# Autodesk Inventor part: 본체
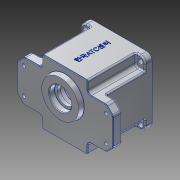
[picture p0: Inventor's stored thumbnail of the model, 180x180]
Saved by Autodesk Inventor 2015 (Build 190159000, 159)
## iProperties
Created: 2016-02
Part Number: 본체
Material: Aluminum 6061
Document SubType Name: Modeling
Designer: Administrator
Density: 2.7 g/cm^3
Appearance: Aluminum - Flat
Mass: 873.756 g
Surface Area: 761.195 cm^2
Volume: 323.613 cm^3
Author: Administrator
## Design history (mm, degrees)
sketch "Sketch1"
  geometry: L1 (-47, -47)-(47, -47); L2 (47, -47)-(47, 47); L3 (47, 47)-(-47, 47); L4 (-47, 47)-(-47, -47); L5 (-47, -47)-(47, 47); L6 (47, -47)-(-47, 47); 1 further point
  constraints: 12 end point, 2 midpoint, 2 parallel, 1 horizontal, 1 perpendicular
  dimensions: "d0" = 94 distance of L3.end L2.end; "d1" = 94 distance of L2.end L1.end
extrude "Extrusion1" new body sketch "Sketch1" distance "d2" = 80; taper "d3" = 0 deg
sketch "Sketch2"
  geometry: L1 (33, -47)-(-33, -47); L2 (-33, -47)-(-33, 47); L3 (-33, 47)-(33, 47); L4 (33, 47)-(33, -47); L5 (33, -47)-(-33, 47); L6 (-33, -47)-(33, 47); L7 (-47, 47)-(47, 47) reference; L8 (47, -30)-(-47, -30); L9 (-47, -30)-(-47, 30); L10 (-47, 30)-(47, 30); L11 (47, 30)-(47, -30); L12 (47, -30)-(-47, 30); L13 (-47, -30)-(47, 30); L14 (47, 47)-(47, -47) reference; L15 (47, -47)-(-47, -47) reference; L16 (-47, -47)-(-47, 47) reference; L17 (-47, 47)-(47, 47) reference; L18 (47, 47)-(47, -47) reference; 1 further point
  constraints: 24 end point, 4 midpoint, 4 parallel, 2 collinear, 2 horizontal, 2 perpendicular
  dimensions: "d4" = 66 distance of L2.end L3.end; "d5" = 60 distance of L8.end L9.end
extrude "Extrusion2" cut sketch "Sketch2" distance "d6" = 70; taper "d7" = 0 deg
sketch "Sketch3"
  geometry: L1 (70, -30)-(-70, -30); L2 (-70, -30)-(-70, 30); L3 (-70, 30)-(70, 30); L4 (70, 30)-(70, -30); L5 (70, -30)-(-70, 30); L6 (-70, -30)-(70, 30); 1 further point
  constraints: 12 end point, 2 midpoint, 2 parallel, 1 horizontal, 1 perpendicular
  dimensions: "d8" = 140 distance of L2.end L3.end; "d9" = 60 distance of L1.end L2.end
extrude "Extrusion3" join sketch "Sketch3" distance "d10" = 13; taper "d11" = 0 deg
fillet "Fillet1" dims "d12" = 8
chamfer "Chamfer1" distance "d13" = 10; stored, may be unused: second distance "d14" = 2, angle "d15" = 45 deg
sketch "Sketch4"
  geometry: C1 r 28 at (0, 11); 1 further point
  constraints: 1 centre point, 1 vertical alignment
  dimensions: "d16" = 56 diameter of C1; "d17" = 11 distance of C1.centre point (0, 0)
extrude "Extrusion4" join sketch "Sketch4" distance "d18" = 7; taper "d19" = -10 deg
sketch "Sketch5"
  geometry: C1 r 43 at (0, 0); 1 further point
  constraints: 1 centre point, 1 coincident
  dimensions: "d20" = 86 diameter of C1
extrude "Extrusion5" cut sketch "Sketch5" distance "d21" = 9; taper "d22" = 0 deg
sketch "Sketch6"
  geometry: C1 r 40 at (0, 0); 1 further point
  constraints: 1 centre point, 1 coincident
  dimensions: "d23" = 80 diameter of C1
extrude "Extrusion6" cut sketch "Sketch6" distance "d24" = 62; taper "d25" = 0 deg
sketch "Sketch7"
  geometry: C1 r 21 at (0, -11); C2 r 15 at (0, 20); 1 further point
  constraints: 2 centre point, 2 vertical alignment
  dimensions: "d26" = 21 radius of C1; "d27" = 15 radius of C2; "d28" = 11 distance of point (0, 0) C1.centre; "d29" = 20 distance of C2.centre point (0, 0)
extrude "Extrusion7" join sketch "Sketch7" distance "d30" = 7; taper "d31" = 0 deg
hole "Hole1" diameter "d34" = 19; stored, may be unused: countersink angle "d38" = 90 deg, drill point angle "d40" = 0 deg; dims "d32" = 10, "d33" = 10, "d35" = 6, "d36" = 22, "d37" = 7, "d39" = 8
sketch "Sketch8"
  geometry: C1 r 17.5 at (0, -11); A1 r 21 centre (0, -11) between (-8.978, 7.984) and (8.978, 7.984) reference; 1 further point
  constraints: 1 centre point, 1 coincident
  dimensions: "d41" = 35 diameter of C1
extrude "Extrusion8" cut sketch "Sketch8" distance "d42" = 10; taper "d43" = 0 deg
hole "Hole2" diameter "d46" = 25; stored, may be unused: countersink angle "d50" = 90 deg, drill point angle "d52" = 0 deg; dims "d44" = 10, "d45" = 10, "d47" = 6, "d48" = 32, "d49" = 8, "d51" = 13
fillet "Fillet2" dims "d53" = 3
sketch "Sketch9"
  geometry: L1 (-35.777, -4)-(-39.799, -4); L2 (-35.777, 4)-(-39.799, 4); L3 (39.799, -4)-(35.777, -4); L4 (39.799, 4)-(35.777, 4); A1 r 36 centre (0, 0) between (36, 0) and (-36, 0); A2 r 40 centre (0, 0) between (-39.799, -4) and (-39.799, 4) reference; A3 r 4 centre (36, 0) between (36, 4) and (36, -4); A4 r 4 centre (-36, 0) between (-36, -4) and (-36, 4); A5 r 40 centre (0, 0) between (39.799, -4) and (39.799, 4); A6 r 40 centre (0, 0) between (-39.799, 4) and (-39.799, -4); 1 further point
  constraints: 18 point on circle, 8 end point, 5 centre point, 4 horizontal, 4 point on line, 4 tangent, 3 coincident, 2 horizontal alignment
  dimensions: "d54" = 36 radius of A1; "d55" = 4 radius of A3; "d56" = 4 radius of A4
extrude "Extrusion9" join sketch "Sketch9" stored distance "d57" = 10; taper "d58" = 0 deg
fillet "Fillet3" dims "d59" = 3.5
sketch "Sketch10"
  geometry: A1 r 4 centre (36, 0) between (35.852, 3.997) and (35.852, -3.997) reference; A2 r 4 centre (-36, 0) between (-35.852, -3.997) and (-35.852, 3.997) reference; 3 further points
  constraints: 2 coincident
hole "Hole3" sketch "Sketch10" at (36, 0), (-36, 0) diameter "d60" = 3.242; stored, may be unused: countersink angle "d64" = 90 deg, drill point angle "d66" = 118 deg; dims "d61" = 7, "d62" = 32, "d63" = 8, "d65" = 9
sketch "Sketch12"
  geometry: 5 further points
  constraints: 2 horizontal alignment, 2 vertical alignment
  dimensions: "d70" = 120 distance of point (60, -19) point (-60, -19); "d71" = 60 horizontal distance of point (0, 0) point (-60, -19); "d72" = 38 distance of point (-60, 19) point (-60, -19); "d73" = 19 vertical distance of point (0, 0) point (-60, -19)
hole "Hole4" sketch "Sketch12" at (60, -19), (60, 19), (-60, -19), (-60, 19) diameter "d74" = 5; stored, may be unused: countersink angle "d78" = 90 deg, drill point angle "d80" = 0 deg; dims "d75" = 6, "d76" = 9, "d77" = 4, "d79" = 13
sketch "Sketch13" dims "d0" = 94, "d1" = 94
  geometry: L1 (0, 0)-(78, 0) reference; 2 further points
  constraints: 1 vertical alignment, 1 other
  dimensions: "d82" = 40 distance from line of L1 point (39, -40)
emboss "Emboss1" sketch "Sketch13" dims "d0" = 94, "d1" = 94, "d83" = 0.5, "d84" = 0
fillet "Fillet4" dims "d85" = 0.3
chamfer "Chamfer2" distance "d86" = 1; stored, may be unused: second distance "d87" = 2, angle "d88" = 45 deg
fillet "Fillet5" dims "d89" = 5
sketch "Sketch14"
  geometry: L1 (-47, -39)-(-47, 39) reference; L2 (-39, 47)-(39, 47) reference; L3 (47, 39)-(47, -39) reference; L4 (39, -47)-(-39, -47) reference; C1 r 3.5 at (-40, 40); C2 r 3.5 at (40, 40); C3 r 3.5 at (40, -40); C4 r 3.5 at (-40, -40); A1 r 8 centre (-39, 39) between (-39, 47) and (-47, 39) reference; A2 r 8 centre (39, 39) between (47, 39) and (39, 47) reference; A3 r 8 centre (39, -39) between (39, -47) and (47, -39) reference; A4 r 8 centre (-39, -39) between (-47, -39) and (-39, -47) reference; A5 r 8 centre (-39, 39) between (-39, 47) and (-47, 39) reference; A6 r 8 centre (39, 39) between (47, 39) and (39, 47) reference; A7 r 8 centre (39, -39) between (39, -47) and (47, -39) reference; 1 further point
  constraints: 4 centre point, 2 horizontal alignment, 2 vertical alignment
  dimensions: "d100" = 7 diameter of C1; "d101" = 7 diameter of C2; "d102" = 7 diameter of C3; "d103" = 7 diameter of C4; "d104" = 80 distance of C2.centre C1.centre; "d105" = 40 horizontal distance of point (0, 0) C2.centre; "d106" = 80 distance of C1.centre C4.centre; "d107" = 40 horizontal distance of point (0, 0) C4.centre
  node "Projected Loop3"
fillet "Fillet6" dims "d96" = 2
sketch "Sketch15"
  geometry: L1 (31, -47)-(-31, -47) reference; L2 (33, -45)-(33, -35) reference; L3 (38, -30)-(57.929, -30) reference; L4 (68.536, -21.464)-(61.464, -28.536) reference; L5 (70, 17.929)-(70, -17.929) reference; L6 (61.464, 28.536)-(68.536, 21.464) reference; L7 (57.929, 30)-(38, 30) reference; L8 (33, 35)-(33, 45) reference; L9 (-31, 47)-(31, 47) reference; L10 (-33, 45)-(-33, 35) reference; L11 (-38, 30)-(-57.929, 30) reference; L12 (-68.536, 21.464)-(-61.464, 28.536) reference; L13 (-70, -17.929)-(-70, 17.929) reference; L14 (-61.464, -28.536)-(-68.536, -21.464) reference; L15 (-57.929, -30)-(-38, -30) reference; L16 (-33, -35)-(-33, -45) reference; L17 (32, 45)-(32, 35); L18 (38, 29)-(57.929, 29); L19 (60.757, 27.828)-(67.828, 20.757); L20 (69, 17.929)-(69, -17.929); L21 (67.828, -20.757)-(60.757, -27.828); L22 (57.929, -29)-(38, -29); L23 (32, -35)-(32, -45); L24 (31, -46)-(-31, -46); L25 (-32, -45)-(-32, -35); L26 (-38, -29)-(-57.929, -29); L27 (-60.757, -27.828)-(-67.828, -20.757); L28 (-69, -17.929)-(-69, 17.929); L29 (-67.828, 20.757)-(-60.757, 27.828); L30 (-57.929, 29)-(-38, 29); L31 (-32, 35)-(-32, 45); L32 (-31, 46)-(31, 46); C1 r 28.252 at (0, 11) reference; C2 r 2.5 at (-60, 19) reference; C3 r 2.5 at (60, 19) reference; C4 r 2.5 at (60, -19) reference; C5 r 2.5 at (-60, -19) reference; A1 r 2 centre (-31, -45) between (-33, -45) and (-31, -47) reference; A2 r 2 centre (31, -45) between (31, -47) and (33, -45) reference; A3 r 5 centre (38, -35) between (38, -30) and (33, -35) reference; A4 r 5 centre (57.929, -25) between (57.929, -30) and (61.464, -28.536) reference; A5 r 5 centre (65, -17.929) between (68.536, -21.464) and (70, -17.929) reference; A6 r 5 centre (65, 17.929) between (70, 17.929) and (68.536, 21.464) reference; A7 r 5 centre (57.929, 25) between (61.464, 28.536) and (57.929, 30) reference; A8 r 5 centre (38, 35) between (33, 35) and (38, 30) reference; A9 r 2 centre (31, 45) between (33, 45) and (31, 47) reference; A10 r 2 centre (-31, 45) between (-31, 47) and (-33, 45) reference; A11 r 5 centre (-38, 35) between (-38, 30) and (-33, 35) reference; A12 r 5 centre (-57.929, 25) between (-57.929, 30) and (-61.464, 28.536) reference; A13 r 5 centre (-65, 17.929) between (-68.536, 21.464) and (-70, 17.929) reference; A14 r 5 centre (-65, -17.929) between (-70, -17.929) and (-68.536, -21.464) reference; A15 r 5 centre (-57.929, -25) between (-61.464, -28.536) and (-57.929, -30) reference; A16 r 5 centre (-38, -35) between (-33, -35) and (-38, -30) reference; A17 r 1 centre (31, 45) between (32, 45) and (31, 46); A18 r 6 centre (38, 35) between (32, 35) and (38, 29); A19 r 4 centre (57.929, 25) between (60.757, 27.828) and (57.929, 29); A20 r 4 centre (65, 17.929) between (69, 17.929) and (67.828, 20.757); A21 r 4 centre (65, -17.929) between (67.828, -20.757) and (69, -17.929); A22 r 4 centre (57.929, -25) between (57.929, -29) and (60.757, -27.828); A23 r 6 centre (38, -35) between (38, -29) and (32, -35); A24 r 1 centre (31, -45) between (31, -46) and (32, -45); A25 r 1 centre (-31, -45) between (-32, -45) and (-31, -46); A26 r 6 centre (-38, -35) between (-32, -35) and (-38, -29); A27 r 4 centre (-57.929, -25) between (-60.757, -27.828) and (-57.929, -29); A28 r 4 centre (-65, -17.929) between (-69, -17.929) and (-67.828, -20.757); A29 r 4 centre (-65, 17.929) between (-67.828, 20.757) and (-69, 17.929); A30 r 4 centre (-57.929, 25) between (-57.929, 29) and (-60.757, 27.828); A31 r 6 centre (-38, 35) between (-38, 29) and (-32, 35); A32 r 1 centre (-31, 45) between (-31, 46) and (-32, 45); 1 further point
  constraints: 32 end point, 32 point on circle, 16 centre point, 31 other
  dimensions: "d97" = 1 distance between parallel lines of L9 L32
extrude "Extrusion12" cut sketch "Sketch15" distance "d98" = 1; taper "d99" = 0 deg
extrude "Extrusion13" cut sketch "Sketch14" stored distance "d108" = 1; taper "d109" = 0 deg
body "Solid1"
node "Projected Loop1"
node "Projected Loop4"
